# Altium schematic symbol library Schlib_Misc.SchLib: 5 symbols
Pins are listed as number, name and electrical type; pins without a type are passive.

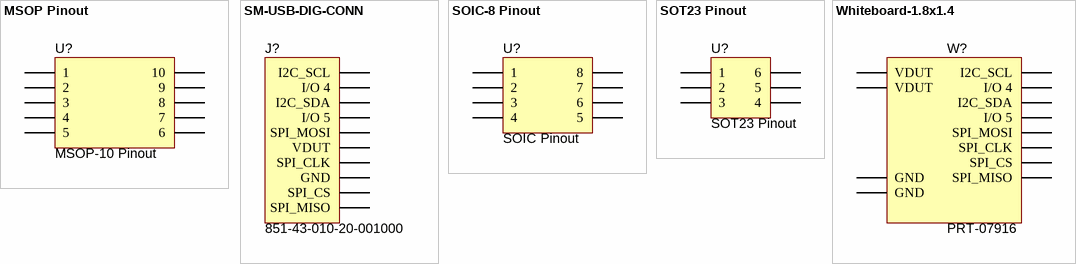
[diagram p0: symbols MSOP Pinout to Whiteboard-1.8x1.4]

## MSOP Pinout
designator U?, comment MSOP-10 Pinout
Blank MSOP-10 schematic symbol; Manufacturer: DNP; SymbolVersion: use current date i.e. 2008-05-20; SymbolCreator: Use LDAP id; U/M: EA, IN, or GM
footprint LDA10A (PSON, 10-Leads, Body 3x3mm, Pitch 0.5mm, NSC Recommended)
pins: 1, 2, 3, 4, 5, 6, 7, 8, 9, 10

## SM-USB-DIG-CONN
designator J?, comment 851-43-010-20-001000
10-Pin 50-mil Connector of SM-USB-DIG; Manufacturer: Mill-Max Manufacturing Corp.; SymbolCreator: Use LDAP id; CompType: Conn; U/M: EA, IN, or GM
footprint 851-43-010-20-001000 (10 Pin connector for SM-USB-DIG)
footprint 850-43-010-20-001000 (Male 10 Pin connector for SM-USB-DIG)
pins: 1 I2C_SCL, 2 I/O 4, 3 I2C_SDA, 4 I/O 5, 5 SPI_MOSI, 6 VDUT, 7 SPI_CLK, 8 GND, 9 SPI_CS, 10 SPI_MISO

## SOIC-8 Pinout
designator U?, comment SOIC Pinout
Manufacturer: DNP; SymbolVersion: use current date i.e. 2008-05-20; SymbolCreator: Use LDAP id; U/M: EA, IN, or GM
footprint M08A_M (SOIC, 8-Leads, Body 4.9x3.9mm, Pitch 1.27mm, IPC Low Density)
pins: 1, 2, 3, 4, 5, 6, 7, 8

## SOT23 Pinout
designator U?
Manufacturer: DNP; SymbolVersion: use current date i.e. 2008-05-20; SymbolCreator: Use LDAP id; U/M: EA, IN, or GM
footprint MK06A_M (SOT23, 6-Leads, Body 3.0x1.7mm, Pitch 0.95mm, Lead Span 2.9mm, IPC Low Density)
pins: 1, 2, 3, 4, 5, 6

## Whiteboard-1.8x1.4
designator W?, comment PRT-07916
Small Bread Board with proto area; Manufacturer: 3M; SymbolCreator: Use LDAP id; CompType: Used in some BOM reports.  Useful for finding later.; U/M: EA, IN, or GM
footprint Whiteboard-1.8x1.4 (Whiteboard with proto area)
pins: 0 VDUT, 1 I2C_SCL, 2 I/O 4, 3 I2C_SDA, 4 I/O 5, 5 SPI_MOSI, 6 VDUT, 7 SPI_CLK, 8 GND, 9 SPI_CS, 10 SPI_MISO (oc), 11 GND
